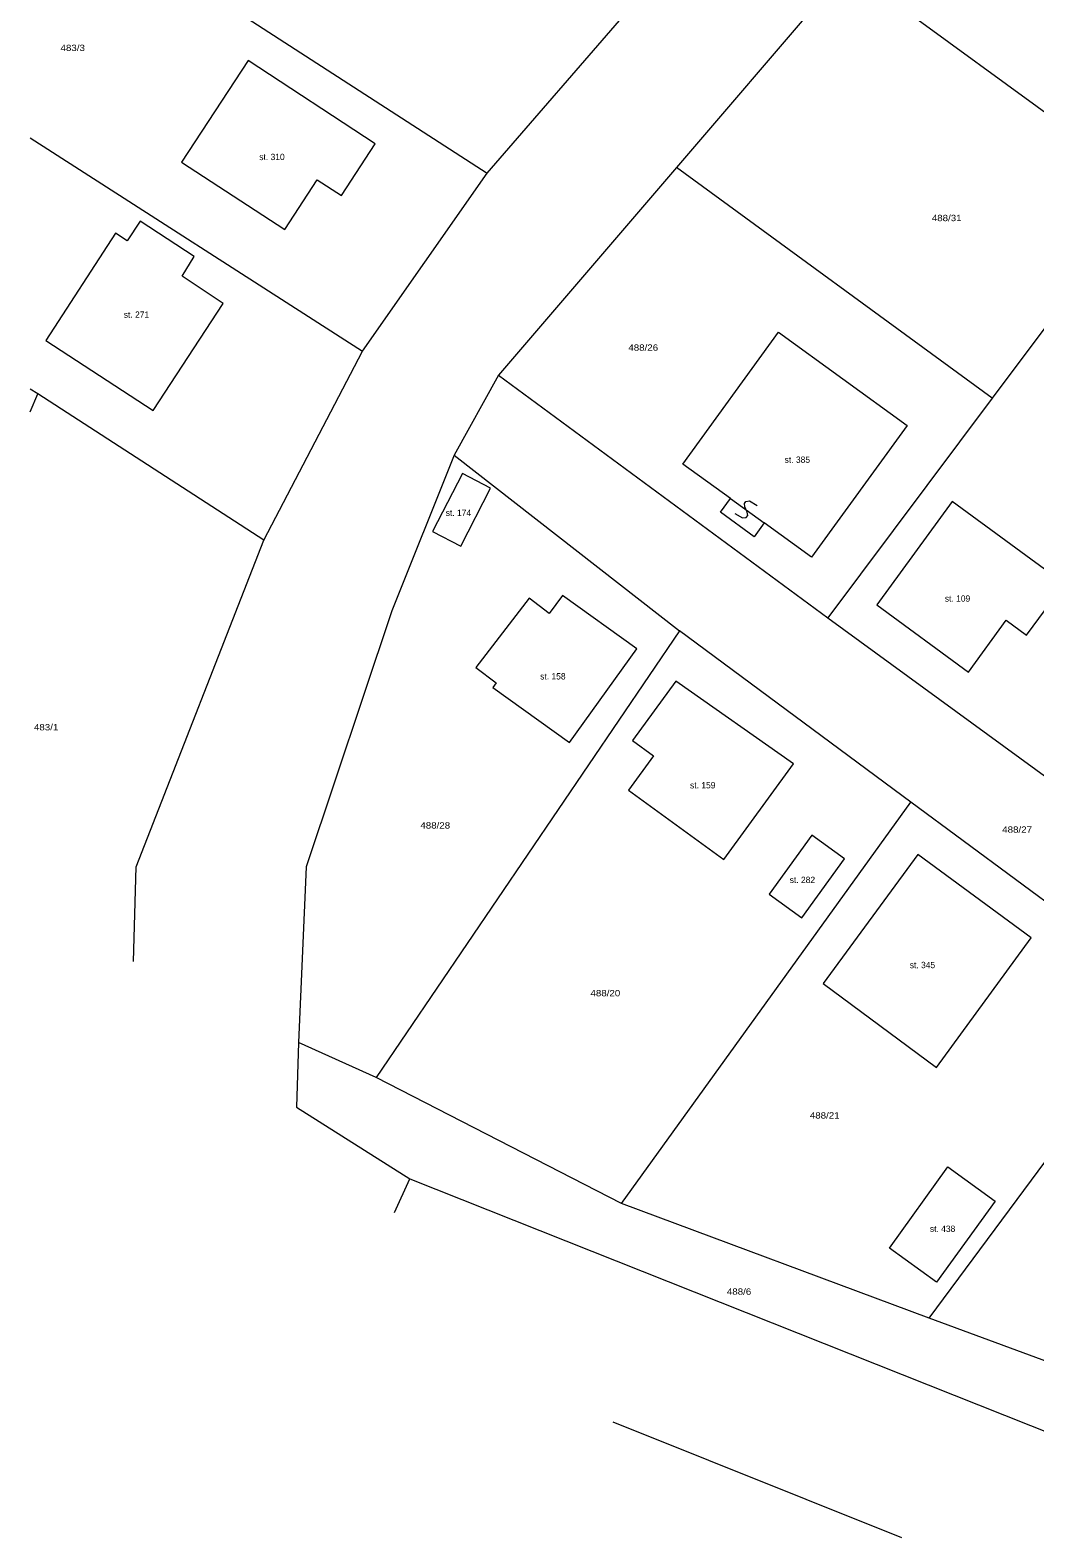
# Model space of a CAD drawing. Extents: x -694702 to -694000, y -1089746 to -1089192.
# Drawn here: x -694701.8 to -694622.5, y -1089606.5 to -1089487.5 of the extents above; entities that cross this region are included whole.
import ezdxf

# ---------------------------------------------------------------- set-up
doc = ezdxf.new("R2010")
doc.units = 0
doc.header["$LTSCALE"] = 0.2
doc.layers.add('50', color=7, linetype='Continuous', lineweight=13)
doc.layers.add('52', color=7, linetype='Continuous', lineweight=13)

msp = doc.modelspace()

# ---------------------------------------------------------------- linework, layer by layer
at = {"layer": '50'}
for p, q in [((-694701.8, -1089475.49), (-694665.71, -1089498.81)), ((-694637.28, -1089482.61), (-694650.77, -1089498.36)), ((-694637.28, -1089482.61), (-694613.45, -1089500)), ((-694665.71, -1089498.81), (-694654.58, -1089485.98)), ((-694701.8, -1089496.03), (-694675.56, -1089512.86)), ((-694675.56, -1089512.86), (-694665.71, -1089498.81)), ((-694650.77, -1089498.36), (-694664.82, -1089514.76)), ((-694625.84, -1089516.56), (-694650.77, -1089498.36)), ((-694613.45, -1089500), (-694625.84, -1089516.56)), ((-694683.34, -1089527.79), (-694675.56, -1089512.86)), ((-694664.82, -1089514.76), (-694668.31, -1089521.06)), ((-694664.82, -1089514.76), (-694638.82, -1089533.91)), ((-694625.84, -1089516.56), (-694638.82, -1089533.91)), ((-694646.51, -1089524.49), (-694643.84, -1089526.42)), ((-694638.82, -1089533.91), (-694614.68, -1089551.51)), ((-694632.26, -1089548.47), (-694650.53, -1089534.93)), ((-694655.1, -1089580.15), (-694632.26, -1089548.47)), ((-694611.84, -1089563.58), (-694632.26, -1089548.47)), ((-694630.82, -1089589.19), (-694611.84, -1089563.58)), ((-694673.024, -1089580.848), (-694671.82, -1089578.19)), ((-694630.82, -1089589.19), (-694655.1, -1089580.15)), ((-694632.98, -1089606.54), (-694655.77, -1089597.42))]:
    msp.add_line(p, q, dxfattribs=at)
for points in [[(-694689.84, -1089497.93), (-694681.7, -1089503.25), (-694679.14, -1089499.33), (-694677.22, -1089500.58), (-694674.57, -1089496.5), (-694684.58, -1089489.93)], [(-694692.09, -1089517.55), (-694686.55, -1089509.09), (-694689.81, -1089506.95), (-694688.85, -1089505.4), (-694693.12, -1089502.61), (-694694.13, -1089504.16), (-694695.05, -1089503.55), (-694700.57, -1089512.01)], [(-694643.84, -1089526.42), (-694644.63, -1089527.52), (-694647.3, -1089525.58), (-694646.51, -1089524.49), (-694650.26, -1089521.77), (-694642.72, -1089511.37), (-694632.55, -1089518.72), (-694640.12, -1089529.13)], [(-694667.67, -1089522.53), (-694670.02, -1089527.11), (-694667.8, -1089528.25), (-694665.45, -1089523.67)], [(-694627.71, -1089538.19), (-694624.73, -1089534.11), (-694623.12, -1089535.29), (-694620.13, -1089531.22), (-694629, -1089524.74), (-694634.96, -1089532.89)], [(-694653.91, -1089536.35), (-694659.76, -1089532.16), (-694660.83, -1089533.56), (-694662.39, -1089532.36), (-694666.6, -1089537.83), (-694665.01, -1089539.05), (-694665.28, -1089539.4), (-694659.21, -1089543.75)], [(-694652.58, -1089544.82), (-694654.56, -1089547.52), (-694647.04, -1089553), (-694641.53, -1089545.44), (-694650.82, -1089538.92), (-694654.24, -1089543.61)], [(-694637.51, -1089552.93), (-694640.09, -1089551.06), (-694643.46, -1089555.72), (-694640.88, -1089557.59)], [(-694639.18, -1089562.79), (-694630.25, -1089569.41), (-694622.76, -1089559.18), (-694631.7, -1089552.6)], [(-694630.23, -1089586.35), (-694633.94, -1089583.66), (-694629.34, -1089577.26), (-694625.61, -1089579.97)]]:
    msp.add_lwpolyline(points, close=True, dxfattribs=at)
for points in [[(-694701.8, -1089517.66), (-694701.2, -1089516.24), (-694701.8, -1089515.87)], [(-694693.649, -1089561.037), (-694693.43, -1089553.56), (-694683.34, -1089527.79), (-694701.2, -1089516.24)], [(-694668.31, -1089521.06), (-694673.23, -1089533.35), (-694680.01, -1089553.57), (-694680.62, -1089567.44)], [(-694668.31, -1089521.06), (-694650.53, -1089534.93), (-694674.48, -1089570.19)], [(-694680.62, -1089567.44), (-694680.78, -1089572.55), (-694671.82, -1089578.19)], [(-694655.1, -1089580.15), (-694674.48, -1089570.19), (-694680.62, -1089567.44)], [(-694671.82, -1089578.19), (-694612.56, -1089601.76), (-694600.32, -1089597.63)], [(-694600.32, -1089597.63), (-694614.98, -1089595.05), (-694630.82, -1089589.19)]]:
    msp.add_lwpolyline(points, dxfattribs=at)
at = {"layer": '52'}
msp.add_lwpolyline([(-694646.156, -1089525.679), (-694645.548, -1089526.027), (-694645.264, -1089525.997), (-694645.136, -1089525.84), (-694645.179, -1089525.559), (-694645.371, -1089525.156), (-694645.405, -1089524.88), (-694645.286, -1089524.718), (-694644.996, -1089524.68), (-694644.394, -1089525.036)], dxfattribs=at)

# ---------------------------------------------------------------- texts
at = {"layer": '52', "width": 1.15}
for s, p in [('483/3', (-694699.4, -1089489.17)), ('488/31', (-694630.61, -1089502.6)), ('488/26', (-694654.57, -1089512.83)), ('483/1', (-694701.5, -1089542.8)), ('488/28', (-694670.99, -1089550.55)), ('488/27', (-694625.05, -1089550.88)), ('488/20', (-694657.56, -1089563.79)), ('488/21', (-694640.24, -1089573.44)), ('488/6', (-694646.79, -1089587.35))]:
    msp.add_text(s, height=0.5, dxfattribs=at).set_placement(p)
at = {"layer": '52'}
for s, p in [('st. 310', (-694683.71, -1089497.78)), ('st. 271', (-694694.41, -1089510.23)), ('st. 385', (-694642.23, -1089521.68)), ('st. 174', (-694668.99, -1089525.87)), ('st. 109', (-694629.58, -1089532.64)), ('st. 158', (-694661.53, -1089538.78)), ('st. 159', (-694649.7, -1089547.38)), ('st. 282', (-694641.83, -1089554.85)), ('st. 345', (-694632.35, -1089561.57)), ('st. 438', (-694630.76, -1089582.39))]:
    msp.add_text(s, height=0.5, dxfattribs=at).set_placement(p)

doc.saveas('drawing.dxf')
